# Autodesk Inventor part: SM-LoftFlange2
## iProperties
Created: 2008-12
Part Number: SM-LoftFlange2
Material: Default
Document SubType Name: Sheet Metal
Designer: Designer
Density: 1 g/cm^3
Sheet Metal Rule: Default_mm
Author: Designer
